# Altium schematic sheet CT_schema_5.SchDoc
size 218 x 258 mm
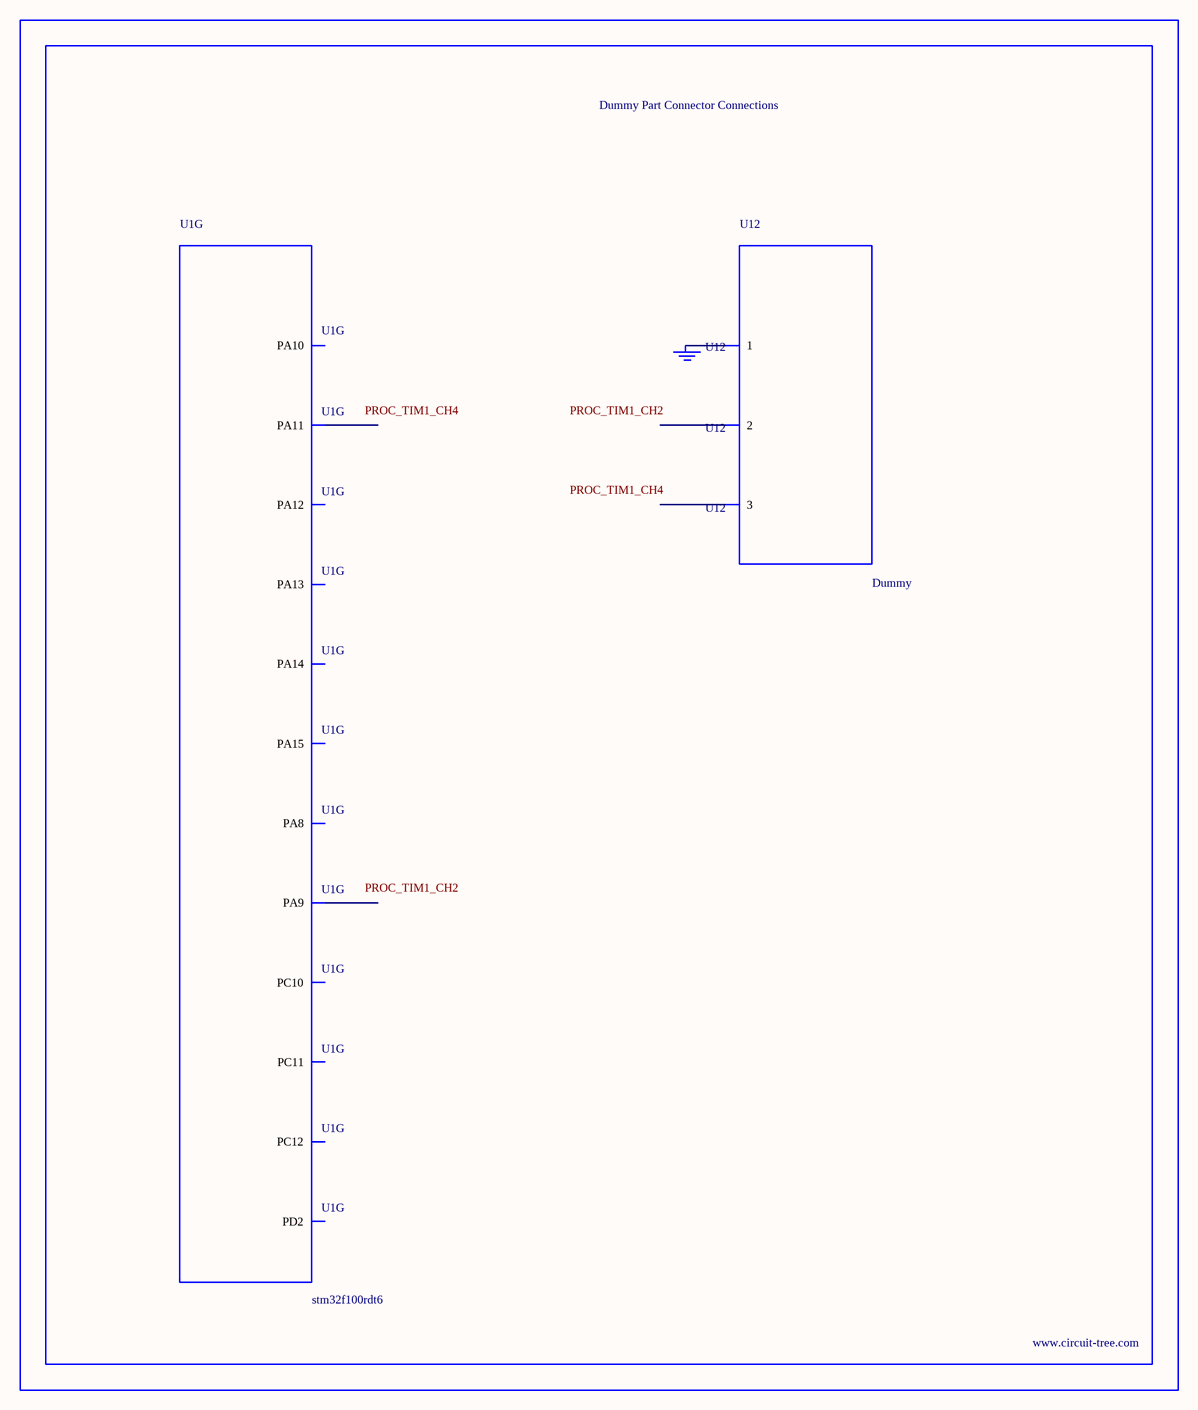
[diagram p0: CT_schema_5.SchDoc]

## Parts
BORDER4  (no value)
GND_INSTANCE_4_0  (no value)
U1  stm32f100rdt6  [LQFP64]  (part G of 7)
U12  Dummy  [DUMMY_PACKAGE_126]

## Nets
NetGND_INSTANCE_4_0_0: GND_INSTANCE_4_0.0(GND) U12.1

Not connected (* = marked no-connect by the designer): U1 41(PA8) 42(PA9) 43(PA10) 44(PA11) 45(PA12) 46(PA13) 49(PA14) 50(PA15) 51(PC10) 52(PC11) 53(PC12) 54(PD2); U12 2 3

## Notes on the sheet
- Labels drawn without touching a wire or pin: PROC_TIM1_CH2, PROC_TIM1_CH4

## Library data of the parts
BORDER4 = BORDER_PAGE4
GND_INSTANCE_4_0 = GND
